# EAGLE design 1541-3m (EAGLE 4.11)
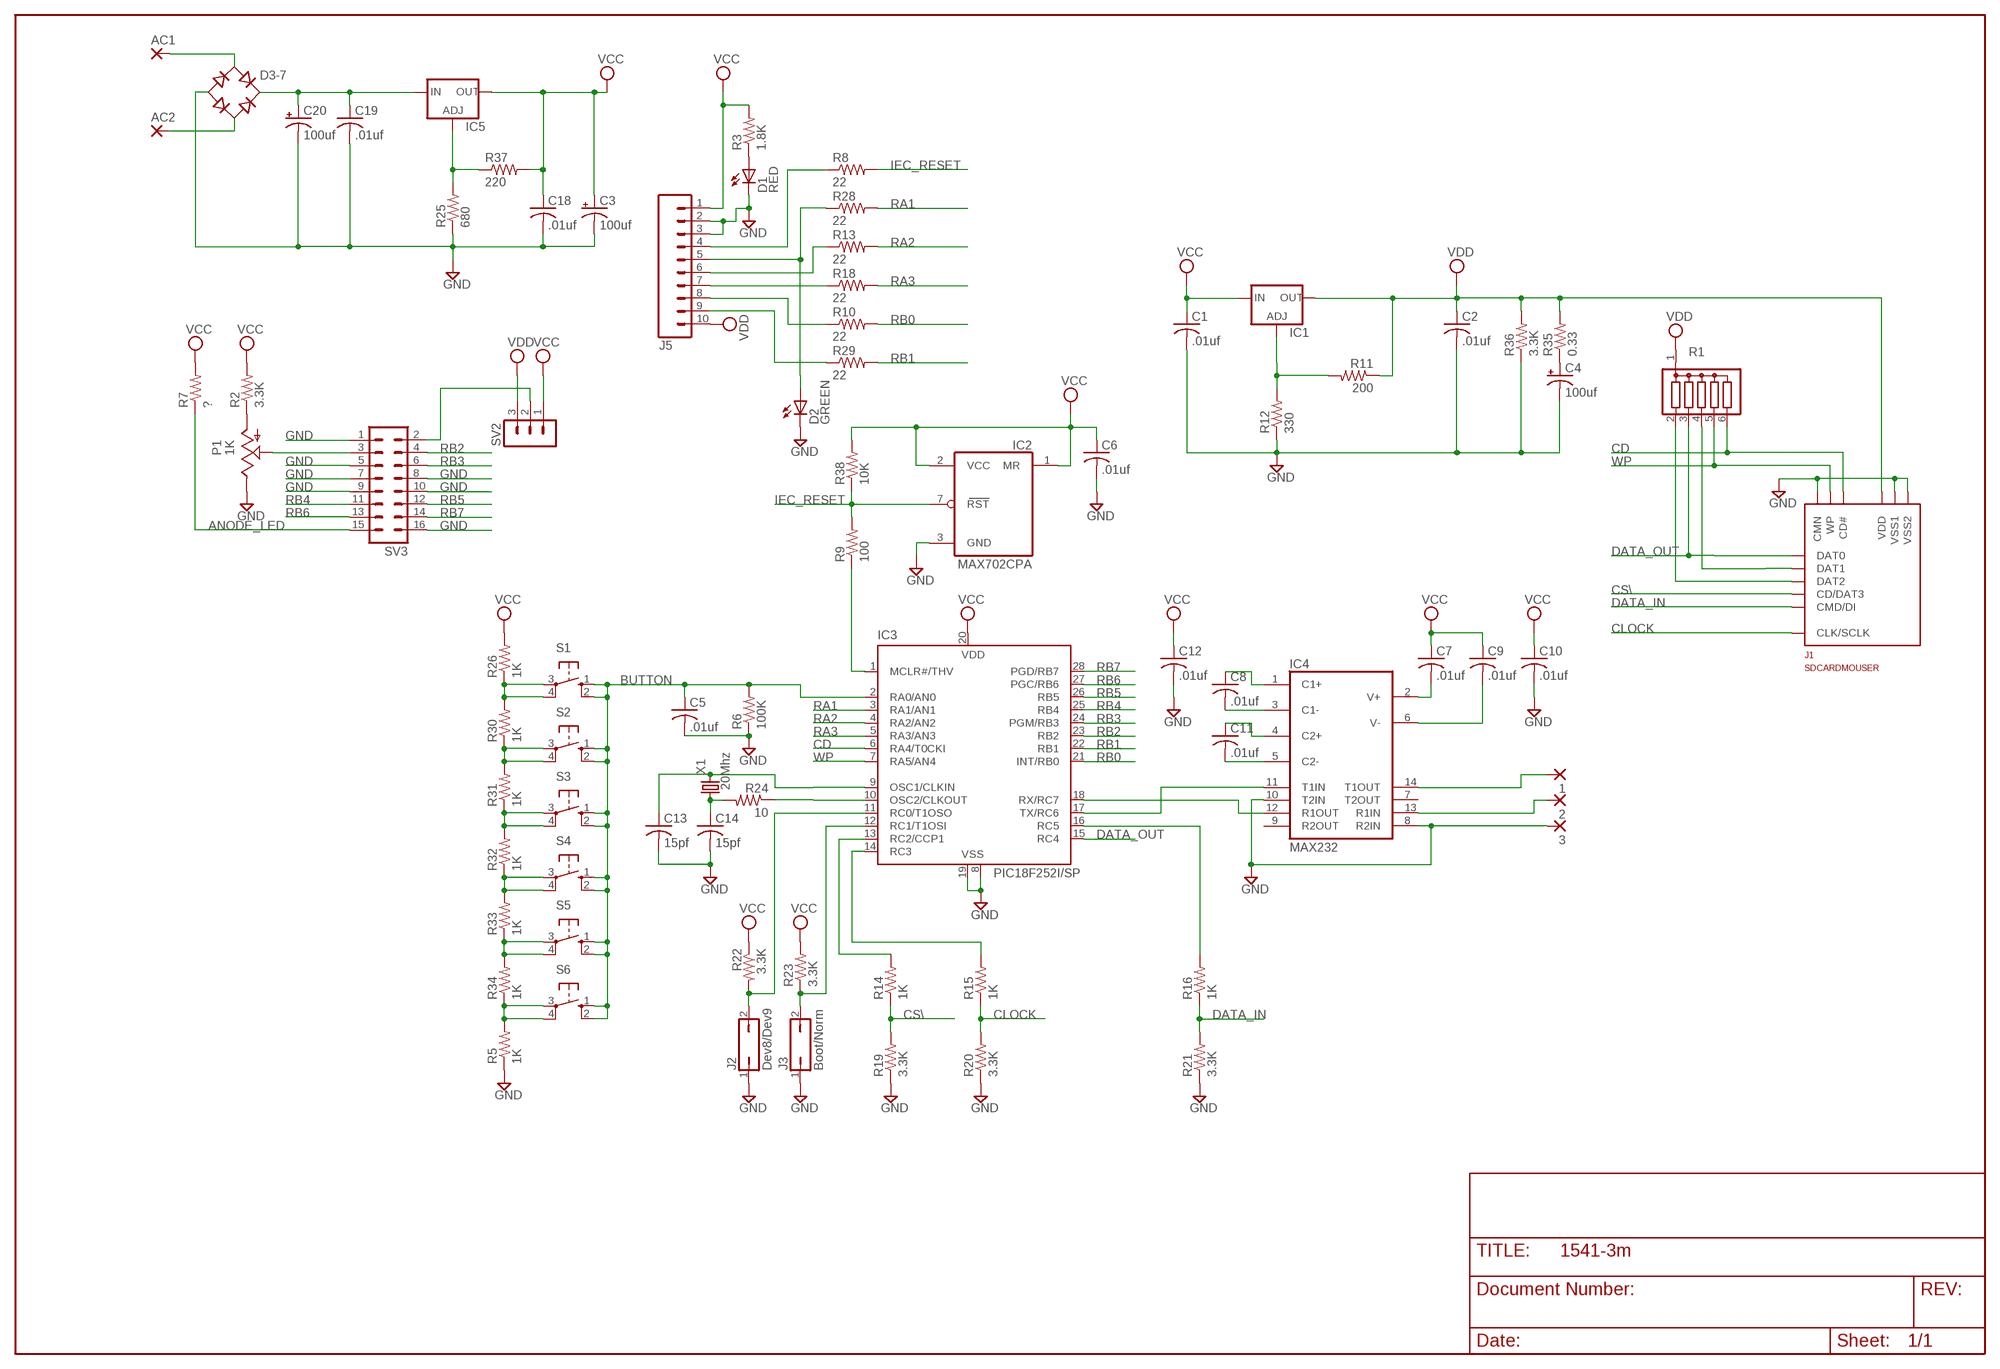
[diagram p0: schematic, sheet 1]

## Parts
1  2,15/1,0  [2,15/1,0]
2  2,15/1,0  [2,15/1,0]
3  2,15/1,0  [2,15/1,0]
AC1  2,15/1,0  [2,15/1,0]
AC2  2,15/1,0  [2,15/1,0]
C1  .01uf  C-US025-024X044  [C025-024X044]
C2  .01uf  C-US025-024X044  [C025-024X044]
C3  100uf  CPOL-USE2-5  [E2-5]
C4  100uf  CPOL-USE2-5  [E2-5]
C5  .01uf  C-US025-024X044  [C025-024X044]
C6  .01uf  C-US025-024X044  [C025-024X044]
C7  .01uf  C-US025-024X044  [C025-024X044]
C8  .01uf  C-US025-024X044  [C025-024X044]
C9  .01uf  C-US025-024X044  [C025-024X044]
C10  .01uf  C-US025-024X044  [C025-024X044]
C11  .01uf  C-US025-024X044  [C025-024X044]
C12  .01uf  C-US025-024X044  [C025-024X044]
C13  15pf  C-US025-024X044  [C025-024X044]
C14  15pf  C-US025-024X044  [C025-024X044]
C18  .01uf  C-US025-024X044  [C025-024X044]
C19  .01uf  C-US025-024X044  [C025-024X044]
C20  100uf  CPOL-USE2-5  [E2-5]
D1  RED  LED3MM  [LED3MM]
D2  GREEN  LED3MM  [LED3MM]
D3-7  RB1A  [RB1A]
IC1  LM317TS  [317TS]
IC2  MAX702CPA  [DIL08]
IC3  PIC18F252I/SP  PIC16F870P  [DIL28-3]
IC4  MAX232  [DIL16]
IC5  LM317TS  [317TS]
J1  SDCARDMOUSER  [SCDA1A]
J2  Dev8/Dev9  JP1Q  [JP1]
J3  Boot/Norm  JP1Q  [JP1]
J5  M10  [10P]
P1  1K  TRIM_US-LI10  [LI10]
R1  G05R  [SIL6]
R2  3.3K  R-US_0207/2V  [0207/2V]
R3  1.8K  R-US_0207/2V  [0207/2V]
R5  1K  R-US_0207/2V  [0207/2V]
R6  100K  R-US_0207/2V  [0207/2V]
R7  ?  R-US_0207/2V  [0207/2V]
R8  22  R-US_0207/2V  [0207/2V]
R9  100  R-US_0207/2V  [0207/2V]
R10  22  R-US_0207/2V  [0207/2V]
R11  200  R-US_0207/2V  [0207/2V]
R12  330  R-US_0207/2V  [0207/2V]
R13  22  R-US_0207/2V  [0207/2V]
R14  1K  R-US_0207/2V  [0207/2V]
R15  1K  R-US_0207/2V  [0207/2V]
R16  1K  R-US_0207/2V  [0207/2V]
R18  22  R-US_0207/2V  [0207/2V]
R19  3.3K  R-US_0207/2V  [0207/2V]
R20  3.3K  R-US_0207/2V  [0207/2V]
R21  3.3K  R-US_0207/2V  [0207/2V]
R22  3.3K  R-US_0207/2V  [0207/2V]
R23  3.3K  R-US_0207/2V  [0207/2V]
R24  10  R-US_0207/2V  [0207/2V]
R25  680  R-US_0207/2V  [0207/2V]
R26  1K  R-US_0207/2V  [0207/2V]
R28  22  R-US_0207/2V  [0207/2V]
R29  22  R-US_0207/2V  [0207/2V]
R30  1K  R-US_0207/2V  [0207/2V]
R31  1K  R-US_0207/2V  [0207/2V]
R32  1K  R-US_0207/2V  [0207/2V]
R33  1K  R-US_0207/2V  [0207/2V]
R34  1K  R-US_0207/2V  [0207/2V]
R35  0.33  R-US_0207/2V  [0207/2V]
R36  3.3K  R-US_0207/2V  [0207/2V]
R37  220  R-US_0207/2V  [0207/2V]
R38  10K  R-US_0207/2V  [0207/2V]
S1  10-XX  [B3F-10XX]
S2  10-XX  [B3F-10XX]
S3  10-XX  [B3F-10XX]
S4  10-XX  [B3F-10XX]
S5  10-XX  [B3F-10XX]
S6  10-XX  [B3F-10XX]
SV2  MA03-1  [MA03-1]
SV3  ML16  [ML16]
X1  20Mhz  CRYTALHC49U70  [HC49U70]

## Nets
ANODE_LED: R7.1 SV3.15
BUTTON: C5.1 IC3.2(RA0/AN0) R6.2 S1.1(S) S1.2(S1) S2.1(S) S2.2(S1) S3.1(S) S3.2(S1) S4.1(S) S4.2(S1) S5.1(S) S5.2(S1) S6.1(S) S6.2(S1)
CD: IC3.6(RA4/T0CKI) J1.10(CD#) R1.6
CLOCK: J1.5(CLK/SCLK) R15.1 R20.2
CS\: J1.1(CD/DAT3) R14.1 R19.2
DATA_IN: J1.2(CMD/DI) R16.1 R21.2
DATA_OUT: IC3.15(RC4) J1.7(DAT0) R1.3
GND: 3.1(P) C1.2 C2.2 C3.- C4.- C5.2 C6.2 C10.2 C12.2 C13.2 C14.2 C18.2 C19.2 C20.- D1.K(C) D2.K(C) D3-7.- IC2.3(GND) IC3.8(VSS) IC3.19(VSS) IC4.8(R2IN) IC4.10(T2IN) J1.3(VSS1) J1.6(VSS2) J1.11(CMN) J2.1 J3.1 J5.2 J5.3 P1.E R5.1 R6.1 R12.1 R19.1 R20.1 R21.1 R25.1 R36.1 SV3.1 SV3.5 SV3.7 SV3.8 SV3.9 SV3.10 SV3.16
IEC_RESET: IC2.7(RST) R8.2 R9.2 R38.1
N$1: C4.+ R35.1
N$2: J1.9(DAT2) R1.2
N$3: J1.8(DAT1) R1.4
N$4: J5.9 R29.1
N$5: J5.8 R10.1
N$6: J5.7 R18.1
N$7: J5.4 R8.1
N$8: D2.A J5.5 R28.1
N$9: J5.6 R13.1
N$10: D1.A R3.1
N$11: IC3.18(RX/RC7) IC4.12(R1OUT)
N$12: IC3.14(RC3) R15.2
N$13: C14.1 R24.2 X1.1
N$14: IC3.1(MCLR#/THV) R9.1
N$15: C11.1 IC4.4(C2+)
N$16: C11.2 IC4.5(C2-)
N$17: C8.2 IC4.3(C1-)
N$18: C8.1 IC4.1(C1+)
N$19: C7.2 IC4.2(V+)
N$20: C13.1 IC3.9(OSC1/CLKIN) X1.2
N$21: IC3.10(OSC2/CLKOUT) R24.1
N$22: IC3.12(RC1/T1OSI) J3.2 R23.1
N$23: IC3.11(RC0/T1OSO) J2.2 R22.2
N$24: IC3.13(RC2/CCP1) R14.2
N$25: IC3.16(RC5) R16.2
N$26: IC1.1(ADJ) R11.2 R12.2
N$27: IC3.17(TX/RC6) IC4.11(T1IN)
N$28: R26.1 R30.2 S1.3(P) S1.4(P1)
N$29: R30.1 R31.2 S2.3(P) S2.4(P1)
N$30: R31.1 R32.2 S3.3(P) S3.4(P1)
N$31: R5.2 R34.1 S6.3(P) S6.4(P1)
N$32: R33.1 R34.2 S5.3(P) S5.4(P1)
N$33: R32.1 R33.2 S4.3(P) S4.4(P1)
N$34: P1.A R2.1
N$35: SV2.2 SV3.2
N$36: P1.S SV3.3
N$37: C9.2 IC4.6(V-)
N$38: IC5.1(ADJ) R25.2 R37.1
N$39: AC1.1(P) D3-7.AC1
N$40: C19.1 C20.+ D3-7.+ IC5.3(IN)
N$41: AC2.1(P) D3-7.AC2
N$42: 2.1(P) IC4.13(R1IN)
N$43: 1.1(P) IC4.14(T1OUT)
RA1: IC3.3(RA1/AN1) R28.2
RA2: IC3.4(RA2/AN2) R13.2
RA3: IC3.5(RA3/AN3) R18.2
RB0: IC3.21(INT/RB0) R10.2
RB1: IC3.22(RB1) R29.2
RB2: IC3.23(RB2) SV3.4
RB3: IC3.24(PGM/RB3) SV3.6
RB4: IC3.25(RB4) SV3.11
RB5: IC3.26(RB5) SV3.12
RB6: IC3.27(PGC/RB6) SV3.13
RB7: IC3.28(PGD/RB7) SV3.14
VCC: C1.1 C3.+ C6.1 C7.1 C9.1 C10.1 C12.1 C18.1 IC1.3(IN) IC2.1(MR) IC2.2(VCC) IC3.20(VDD) IC5.2(OUT) J5.1 R2.2 R3.2 R7.2 R22.1 R23.2 R26.2 R37.2 R38.2 SV2.1
VDD: C2.1 IC1.2(OUT) J1.4(VDD) J5.10 R1.1 R11.1 R35.2 R36.2 SV2.3
WP: IC3.7(RA5/AN4) J1.12(WP) R1.5
Unconnected: IC4.7(T2OUT) IC4.9(R2OUT)

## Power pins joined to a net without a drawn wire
GND: IC4.15(GND) J1.13(GND) J1.14(GND)
VCC: IC4.16(VCC)

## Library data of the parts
1-3 AC1 AC2 = wirepad:2,15/1,0: THROUGH-HOLE PAD
C1 C2 C5-C14 C18 C19 = rcl:C-US: CAPACITOR, American symbol
C3 C4 C20 = rcl:CPOL-US: POLARIZED CAPACITOR, American symbol
D1 D2 = led:LED: LED
D3-7 = rectifier:RB1A: RECTIFIER 1 A
IC1 IC5 = v-reg:LM317TS: VOLTAGE REGULATOR
IC2 = maxim:MAX702CPA: POWER SUPPLY MONITOR
IC3 = microchip:PIC16*870: MICROCONTROLLER flash type
IC4 = maxim:MAX232: RS232 TRANSEIVER
J1 = sdcards:SDCARD: SD Card Holder
J2 J3 = jumper:JP1Q: JUMPER
J5 = con-amp-quick:M10: AMP QUICK CONNECTOR
P1 = pot:TRIM_US-: POTENTIOMETER
R1 = resistor-sil:G05R: SIL RESISTOR
R2 R3 R5-R16 R18-R26 R28-R38 = rcl:R-US_: RESISTOR, American symbol
S1-S6 = switch-omron:10-XX: OMRON SWITCH
SV2 = con-lstb:MA03-1: PIN HEADER
SV3 = con-harting-ml:ML16: HARTING
X1 = crystal:CRYTAL: CRYSTAL

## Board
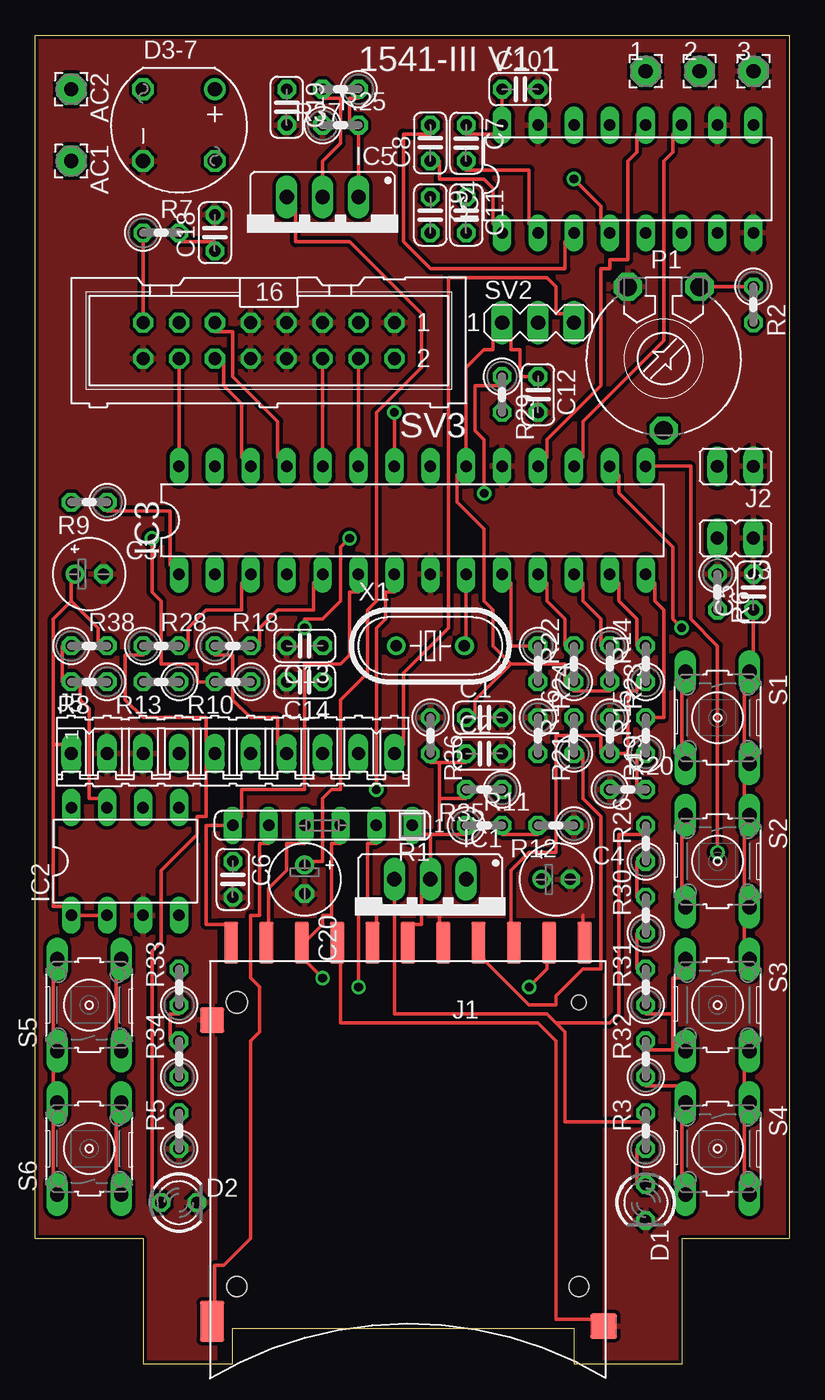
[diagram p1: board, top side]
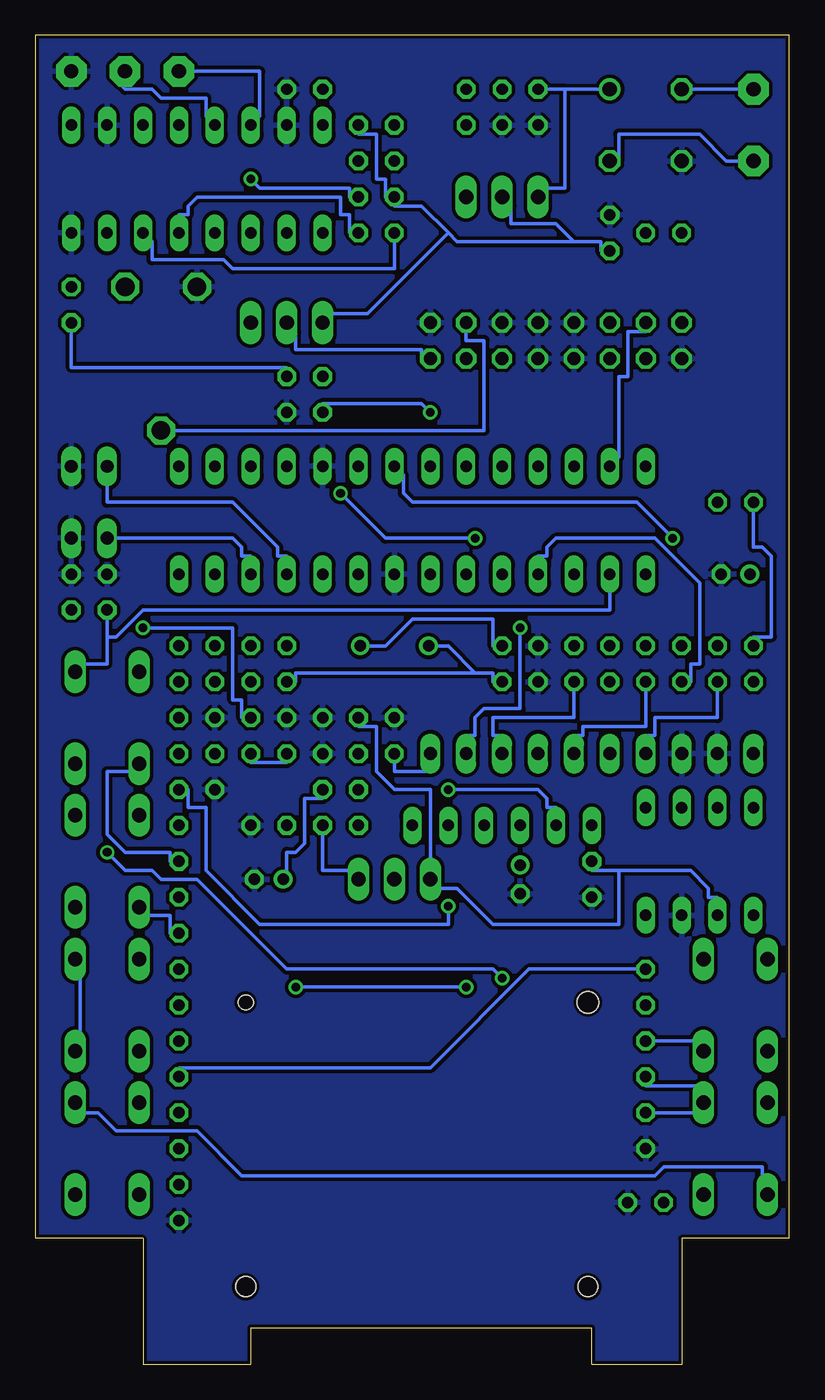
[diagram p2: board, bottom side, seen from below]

Size 53.34 x 93.98 mm. Coordinates in mm from the lower left corner, seen from the top.
Outline: 0,93.98 53.34,93.98 53.34,8.89 45.72,8.89 45.72,0 38.1,0 38.1,2.54 13.97,2.54 13.97,0 7.62,0 7.62,8.89 0,8.89 0,93.98
Copper layers (1*16): Top 0.035mm / dielectric 1.5mm / Bottom 0.035mm
Design rules "olimex10mil": minimum track width 10mil, minimum drill 24mil, track to track 10mil, track to pad 10mil, pad to pad 10mil, via to via 10mil, smd to smd 10mil, copper to edge 10mil, drill to drill 10mil, minimum pad ring 10mil, minimum via ring 8mil, stop-mask expansion 0mil, vias tented up to drill 0mil, thermal gap 10mil

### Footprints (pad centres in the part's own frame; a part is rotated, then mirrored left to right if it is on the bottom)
2,15/1,0 = drill 1.016 pad 2.159 octagon: 1 0,0
C025-024X044 = drill 0.813 octagon: 1 -1.27,0; 2 1.27,0
E2-5 = drill 0.813 pad 1.27 round: + -1.016,0 | drill 0.813 pad 1.27 octagon: - 1.016,0
LED3MM = drill 0.813 octagon: A -1.27,0; K 1.27,0
RB1A = drill 1.016 round: + -2.54,2.54 | drill 1.016 octagon: - 2.54,-2.54; AC1 2.54,2.54; AC2 -2.54,-2.54
317TS = drill 1.016 long: 1 -2.54,-2.54; 2 0,-2.54; 3 2.54,-2.54
DIL08 = drill 0.813 long: 1 -3.81,-3.81; 2 -1.27,-3.81; 3 1.27,-3.81; 4 3.81,-3.81; 5 3.81,3.81; 6 1.27,3.81; 7 -1.27,3.81; 8 -3.81,3.81
DIL28-3 = drill 0.813 long: 1 -16.51,-3.81; 2 -13.97,-3.81; 3 -11.43,-3.81; 4 -8.89,-3.81; 5 -6.35,-3.81; 6 -3.81,-3.81; 7 -1.27,-3.81; 8 1.27,-3.81; 9 3.81,-3.81; 10 6.35,-3.81; 11 8.89,-3.81; 12 11.43,-3.81; 13 13.97,-3.81; 14 16.51,-3.81; 15 16.51,3.81; 16 13.97,3.81; 17 11.43,3.81; 18 8.89,3.81; 19 6.35,3.81; 20 3.81,3.81; 21 1.27,3.81; 22 -1.27,3.81; 23 -3.81,3.81; 24 -6.35,3.81; 25 -8.89,3.81; 26 -11.43,3.81; 27 -13.97,3.81; 28 -16.51,3.81
DIL16 = drill 0.813 long: 1 -8.89,-3.81; 2 -6.35,-3.81; 3 -3.81,-3.81; 4 -1.27,-3.81; 5 1.27,-3.81; 6 3.81,-3.81; 7 6.35,-3.81; 8 8.89,-3.81; 9 8.89,3.81; 10 6.35,3.81; 11 3.81,3.81; 12 1.27,3.81; 13 -1.27,3.81; 14 -3.81,3.81; 15 -6.35,3.81; 16 -8.89,3.81
SCDA1A = smd 1 x 2.95: 1 -7.5,-10.125; 2 -5,-10.125; 3 -2.5,-10.125; 4 0,-10.125; 5 2.5,-10.125; 6 5,-10.125; 7 7.5,-10.125; 8 10,-10.125; 9 -10,-10.125; 10 12.5,-10.125; 13 -12.5,-10.125 | smd 1.7 x 1.8: 11 13.85,-4.65 | smd 1.7 x 2.9: 12 13.85,16.65 | smd 1.9 x 1.8: 14 -13.85,17 | hole 1.05: -12.1,-5.9 | hole 1.5: 12.1,-5.9 | hole 1.4: 12.1,14.2; -12.1,14.2
JP1 = drill 0.914 long: 1 0,-1.27; 2 0,1.27
10P = drill 0.914 long: 1 -11.43,0; 2 -8.89,0; 3 -6.35,0; 4 -3.81,0; 5 -1.27,0; 6 1.27,0; 7 3.81,0; 8 6.35,0; 9 8.89,0; 10 11.43,0
LI10 = drill 1.321 octagon: A -2.54,-5.08; E 2.54,-5.08; S 0,5.08
SIL6 = drill 0.813 long: 1 -6.35,0; 2 -3.81,0; 3 -1.27,0; 4 1.27,0; 5 3.81,0; 6 6.35,0
0207/2V = drill 0.813 octagon: 1 -1.27,0; 2 1.27,0
B3F-10XX = drill 1.016 long: 1 -3.251,2.261; 2 3.251,2.261; 3 -3.251,-2.261; 4 3.251,-2.261
MA03-1 = drill 1.016 long: 1 -2.54,0; 2 0,0; 3 2.54,0
ML16 = drill 0.914 octagon: 1 -8.89,-1.27; 2 -8.89,1.27; 3 -6.35,-1.27; 4 -6.35,1.27; 5 -3.81,-1.27; 6 -3.81,1.27; 7 -1.27,-1.27; 8 -1.27,1.27; 9 1.27,-1.27; 10 1.27,1.27; 11 3.81,-1.27; 12 3.81,1.27; 13 6.35,-1.27; 14 6.35,1.27; 15 8.89,-1.27; 16 8.89,1.27
HC49U70 = drill 0.813 round: 1 -2.413,0; 2 2.413,0

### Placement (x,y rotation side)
1  43.18,91.44 0 top
2  46.99,91.44 0 top
3  50.8,91.44 0 top
AC1  2.54,85.09 270 top
AC2  2.54,90.17 270 top
C1  31.75,45.72 0 top
C2  31.75,43.18 0 top
C3  3.81,55.88 0 top
C4  36.83,34.29 0 top
C5  50.8,54.61 90 top
C6  13.97,34.29 270 top
C7  30.48,86.36 270 top
C8  27.94,86.36 90 top
C9  27.94,81.28 270 top
C10  34.29,90.17 0 top
C11  30.48,81.28 270 top
C12  35.56,68.58 270 top
C13  19.05,50.8 180 top
C14  19.05,48.26 180 top
C18  12.7,80.01 90 top
C19  17.78,88.9 270 top
C20  19.05,34.29 270 top
D1  43.18,11.43 270 top
D2  10.16,11.43 0 top
D3-7  10.16,87.63 270 top
IC1  27.94,31.75 180 top
IC2  6.35,35.56 0 top
IC3  26.67,59.69 0 top
IC4  41.91,83.82 0 top
IC5  20.32,80.01 180 top
J1  26.35,19.68 180 top
J2  49.53,63.5 90 top
J3  49.53,58.42 90 top
J5  13.97,43.18 0 top
P1  44.45,71.12 180 top
R1  20.32,38.1 180 top
R2  50.8,74.93 270 top
R3  43.18,16.51 90 top
R5  10.16,16.51 90 top
R6  48.26,54.61 270 top
R7  8.89,80.01 0 top
R8  3.81,48.26 180 top
R9  3.81,60.96 180 top
R10  13.97,48.26 180 top
R11  31.75,38.1 0 top
R12  36.83,38.1 180 top
R13  8.89,48.26 180 top
R14  43.18,49.53 90 top
R15  43.18,44.45 90 top
R16  38.1,44.45 90 top
R18  13.97,50.8 0 top
R19  40.64,44.45 270 top
R20  41.91,40.64 0 top
R21  35.56,44.45 270 top
R22  38.1,49.53 90 top
R23  40.64,49.53 270 top
R24  35.56,49.53 270 top
R25  21.59,87.63 0 top
R26  43.18,36.83 90 top
R28  8.89,50.8 0 top
R29  33.02,68.58 270 top
R30  43.18,31.75 90 top
R31  43.18,26.67 90 top
R32  43.18,21.59 90 top
R33  10.16,26.67 90 top
R34  10.16,21.59 90 top
R35  31.75,40.64 180 top
R36  27.94,44.45 270 top
R37  21.59,90.17 180 top
R38  3.81,50.8 0 top
S1  48.26,45.72 270 top
S2  48.26,35.56 270 top
S3  48.26,25.4 270 top
S4  48.26,15.24 270 top
S5  3.81,25.4 90 top
S6  3.81,15.24 90 top
SV2  35.56,73.66 0 top
SV3  16.51,72.39 180 top
X1  27.94,50.8 0 top

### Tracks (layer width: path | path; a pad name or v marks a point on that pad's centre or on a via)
ANODE_LED
  Top 0.254: R7.1 7.62,79.38 7.62,74.3 SV3.15
BUTTON
  Top 0.254: C5.1 50.8,52.7 50.8,50.16 S1.1 50.16,47.62 50.16,43.81 S1.2 50.16,41.27 50.16,40.01 S2.1 50.16,37.47 50.16,33.66 S2.2 50.16,31.11 50.16,29.84 S3.1 | S6.1 1.27,13.34 1.27,17.14 S6.2 1.27,19.68 1.27,20.95 S5.1 1.27,23.5 1.27,27.3 S5.2 | S4.2 50.16,13.34 50.16,17.14 S4.1 50.16,19.68 50.16,20.95 S3.2
  Bottom 0.254: 48.26,51.44 48.26,49.53 50.16,49.53 S1.1 | 48.26,51.44 48.26,52.7 R6.2 | 48.26,51.44 47.62,51.44 45.72,53.34 12.7,53.34 12.7,54.61 IC3.2 | S3.2 50.16,23.5 50.16,27.3 S3.1 | S6.1 1.91,13.34 1.91,13.97 8.89,13.97 9.53,13.34 38.73,13.34 41.91,16.51 47.62,16.51 48.9,17.78 50.16,17.78 S4.1
CD
  Top 0.254: J1.10 13.97,31.11 12.06,31.11 12.06,38.1 13.34,38.1 R1.6 14.61,38.73 14.61,40.64 19.05,40.64 19.05,49.53 21.59,49.53 22.23,50.16 22.23,54.61 22.86,54.61 IC3.6
CLOCK  (via drill 0.61)
  Top 0.254: R20.2 42.55,40.64 42.55,43.18 R15.1 | v24.13,32.38 24.13,31.11 J1.5
  Bottom 0.254: v24.13,32.38 24.13,31.11 37.47,31.11 41.27,34.92 41.27,39.37 42.55,39.37 42.55,40.64 R20.2
CS\
  Top 0.254: R14.1 42.55,48.26 42.55,47.62 41.91,47.62 41.91,43.18 41.27,43.18 R19.2 40.01,43.18 40.01,44.45 36.83,44.45 36.83,36.2 34.92,36.2 33.66,34.92 33.66,31.11 J1.1
DATA_IN
  Top 0.254: J1.2 31.75,28.57 34.92,25.4 36.83,25.4 36.83,26.04 38.73,27.94 40.01,27.94 40.01,38.73 38.73,40.01 38.73,43.18 R16.1
  Bottom 0.254: R21.2 35.56,42.55 38.1,42.55 R16.1
DATA_OUT  (via drill 0.61)
  Top 0.254: R1.3 21.59,36.83 20.95,36.83 20.95,31.75 20.32,31.75 20.32,31.11 19.05,29.84 J1.7 19.05,28.57 v20.32,27.3 | v48.26,36.2 48.26,50.8 46.35,52.7 46.35,63.5 43.81,63.5 IC3.15
  Bottom 0.254: v48.26,36.2 46.99,34.92 45.09,34.92 44.45,34.29 41.91,34.29 35.56,27.94 20.95,27.94 v20.32,27.3
GND
  Top 0.254: 40.41,1.91 40.64,1.91 J1.14 39.37,3.17 36.83,3.17 36.83,22.86 35.56,24.13 21.59,24.13 21.59,28.57 J1.6 | 28.57,31.75 28.57,31.11 J1.3 | 38.73,31.75 38.73,31.11 J1.13
  pour Bottom: 0,0 53.34,0 53.34,93.98 0,93.98
  pour Top: 0,0 12.7,0 12.7,31.75 40.32,31.75 40.32,0 53.34,0 53.34,93.98 0,93.98
IEC_RESET
  Top 0.254: R38.1 1.91,50.8 1.91,48.26 R8.2 3.17,48.26 3.17,46.99 3.81,46.35 3.81,40.01 4.45,40.01 IC2.7
  Bottom 0.254: R9.2 2.54,60.33 2.54,57.78 1.91,57.78 1.27,57.15 1.27,51.44 2.54,51.44 R38.1
N$1
  Bottom 0.254: C4.+ 35.56,34.92 35.56,36.2 34.92,36.2 34.29,36.83 34.29,40.01 33.02,40.01 R35.1
N$2  (via drill 0.61)
  Top 0.254: v22.86,26.67 22.86,32.38 23.5,33.02 23.5,36.83 24.13,36.83 R1.2 | v34.92,26.67 36.2,27.94 36.2,28.57 J1.9
  Bottom 0.254: v22.86,26.67 v34.92,26.67
N$3
  Top 0.254: R1.4 19.05,36.83 17.78,36.83 17.78,34.92 16.51,33.66 16.51,31.11 J1.8
N$4  (via drill 0.61)
  Top 0.254: v31.75,61.59 31.75,65.41 31.11,66.04 31.11,69.22 33.02,69.22 R29.1 | v22.23,58.42 21.59,57.78 21.59,53.98 20.32,52.7 19.05,52.7 v19.05,52.07
  Bottom 0.254: v31.75,61.59 28.57,58.42 v22.23,58.42 | v19.05,52.07 19.05,46.35 21.59,46.35 22.23,45.72 22.23,44.45 22.86,44.45 J5.9
N$5
  Bottom 0.254: R10.1 15.24,47.62 15.24,45.72 20.95,45.72 20.95,44.45 20.32,44.45 J5.8
N$6
  Top 0.254: R18.1 12.7,50.16 13.97,50.16 13.97,46.99 15.24,45.72 17.14,45.72 17.14,43.81 J5.7
N$7
  Bottom 0.254: R8.1 5.08,47.62 5.08,45.72 9.53,45.72 9.53,44.45 10.16,44.45 J5.4
N$8
  Top 0.254: D2.A 8.26,11.43 8.26,29.21 8.89,29.84 8.89,34.92 11.43,37.47 11.43,38.73 12.06,38.73 12.06,42.55 J5.5 12.06,43.81 12.06,45.72 7.62,45.72 6.35,46.99 6.35,50.16 7.62,50.16 R28.1
N$9
  Bottom 0.254: R13.1 10.16,47.62 10.16,45.09 14.61,45.09 14.61,44.45 15.24,44.45 J5.6
N$10
  Top 0.254: D1.A 42.55,12.7 42.55,15.24 R3.1
N$11
  Top 0.254: IC3.18 36.2,64.14 36.2,65.41 40.01,69.22 40.01,77.47 40.64,77.47 40.64,78.11 41.91,78.11 41.91,85.09 42.55,85.72 42.55,87 IC4.12
N$12
  Top 0.254: R15.2 43.81,45.72 44.45,45.72 44.45,53.34 43.81,53.98 43.81,55.24 IC3.14
N$13
  Bottom 0.254: 22.23,48.9 20.95,48.9 20.95,48.26 C14.1 | 22.23,48.9 24.13,50.8 25.4,50.8 X1.1 | 22.23,48.9 34.92,48.9 34.92,48.26 R24.2
N$14
  Top 0.254: R9.1 5.08,60.33 9.53,60.33 9.53,56.52 IC3.1
N$15  (via drill 0.61)
  Top 0.254: v38.1,83.82 40.01,81.92 40.01,80.64 IC4.4
  Bottom 0.254: v38.1,83.82 37.47,83.19 31.11,83.19 31.11,82.55 C11.1
N$16
  Bottom 0.254: C11.2 31.11,80.01 31.11,81.28 31.75,81.28 31.75,82.55 41.91,82.55 42.55,81.92 42.55,81.28 43.18,81.28 IC4.5
N$17
  Top 0.254: C8.2 27.94,87 26.04,87 26.04,79.38 27.94,77.47 37.47,77.47 37.47,79.38 IC4.3
N$18
  Top 0.254: IC4.1 32.38,80.64 32.38,83.19 31.75,83.82 28.57,83.82 28.57,85.09 C8.1
N$19
  Top 0.254: C7.2 30.48,84.45 34.92,84.45 34.92,80.64 IC4.2
N$20
  Top 0.254: IC3.9 30.48,54.61 30.48,51.44 X1.2
  Bottom 0.254: C13.1 20.95,50.8 20.95,52.7 26.67,52.7 28.57,50.8 29.84,50.8 X1.2
N$21
  Top 0.254: R24.1 34.92,50.8 33.66,50.8 33.66,55.24 IC3.10
N$22
  Top 0.254: R23.1 40.01,50.8 40.01,52.7 38.73,53.98 38.73,55.24 IC3.12
  Bottom 0.254: J3.2 47.62,58.42 39.37,58.42 38.73,57.78 38.73,57.15 38.1,57.15 IC3.12
N$23
  Top 0.254: R22.2 37.47,50.8 37.47,52.7 36.2,53.98 36.2,55.24 IC3.11
  Bottom 0.254: J2.2 48.26,62.23 48.26,60.96 39.37,60.96 36.2,57.78 36.2,57.15 35.56,57.15 IC3.11
N$24
  Top 0.254: R14.2 42.55,50.8 42.55,52.7 41.27,53.98 41.27,55.24 IC3.13
N$25  (via drill 0.61)
  Top 0.254: v45.72,52.07 45.09,52.7 45.09,57.78 41.27,61.59 41.27,62.87 IC3.16
  Bottom 0.254: v45.72,52.07 39.37,52.07 39.37,46.99 38.73,46.99 38.73,45.72 R16.2
N$26
  Top 0.254: R12.2 35.56,37.47 33.02,37.47 R11.2
  Bottom 0.254: R11.2 33.02,37.47 33.02,34.92 31.11,34.92 IC1.1
N$27
  Top 0.254: IC3.17 38.73,64.14 38.73,66.67 44.45,72.39 44.45,85.09 45.09,85.72 45.09,87 IC4.11
N$28
  Top 0.254: R30.2 42.55,33.02 42.55,35.56 R26.1 | S1.4 45.72,43.81 45.72,47.62 S1.3
  Bottom 0.254: R26.1 43.81,35.56 43.81,36.2 46.99,36.2 48.26,37.47 48.26,41.91 46.35,41.91 S1.4
N$29
  Top 0.254: R31.2 42.55,27.94 42.55,30.48 R30.1 | S2.4 45.72,33.66 45.72,37.47 S2.3
  Bottom 0.254: R30.1 43.81,30.48 43.81,31.75 45.72,31.75 S2.4
N$30
  Top 0.254: 45.09,22.23 45.72,22.23 S3.4 | 45.09,22.23 43.18,22.23 R32.2 | 45.09,24.77 43.18,24.77 R31.1 | 45.09,22.23 45.09,24.77 | 45.09,24.77 45.09,27.3 45.72,27.3 S3.3
N$31
  Top 0.254: S6.3 5.71,13.34 5.71,17.14 S6.4
  Bottom 0.254: R5.2 9.53,17.78 6.35,17.78 S6.4 6.35,19.68 10.16,19.68 R34.1
N$32
  Top 0.254: R33.1 10.16,24.77 9.53,24.77 9.53,22.86 R34.2 | S5.4 5.71,27.3 5.71,23.5 S5.3
  Bottom 0.254: R34.2 9.53,22.86 6.35,22.86 S5.3
N$33
  Top 0.254: S4.4 45.72,13.34 45.72,17.14 S4.3 45.72,19.68 43.18,19.68 R32.1
  Bottom 0.254: R33.2 10.79,27.94 18.41,27.94 25.4,20.95 43.18,20.95 R32.1
N$34
  Top 0.254: R2.1 50.16,76.2 47.62,76.2 P1.A
N$35
  Bottom 0.254: SV3.2 26.04,71.12 26.04,71.75 34.92,71.75 34.92,73.03 SV2.2
N$36
  Bottom 0.254: SV3.3 22.86,73.03 22.86,72.39 21.59,72.39 21.59,66.04 43.81,66.04 P1.S
N$37
  Bottom 0.254: C9.2 27.94,79.38 27.94,77.47 39.37,77.47 40.01,78.11 45.09,78.11 45.09,79.38 IC4.6
N$38
  Top 0.254: IC5.1 22.86,83.82 22.86,87 R25.2 22.23,87.63 22.23,89.53 22.86,89.53 R37.1
N$39
  Bottom 0.254: D3-7.AC1 12.06,85.09 12.06,87 6.35,87 4.45,85.09 3.17,85.09 AC1.1
N$40
  Top 0.254: C20.+ 19.68,35.56 20.32,35.56 20.32,40.01 20.95,40.64 21.59,40.64 21.59,46.99 23.5,48.9 23.5,53.34 24.13,53.98 24.13,67.31 27.3,70.48 27.3,74.3 22.23,79.38 18.41,79.38 18.41,81.92 IC5.3
  Bottom 0.254: 15.88,90.17 13.34,90.17 D3-7.+ | 15.88,90.17 17.14,90.17 C19.1 | 15.88,90.17 15.88,83.19 17.14,83.19 IC5.3
N$41
  Bottom 0.254: D3-7.AC2 6.99,90.17 3.17,90.17 AC2.1
N$42
  Bottom 0.254: IC4.13 41.27,88.27 41.27,89.53 44.45,89.53 45.09,90.17 46.99,90.17 47.62,90.81 2.1
N$43
  Bottom 0.254: IC4.14 37.47,88.27 37.47,91.44 42.55,91.44 1.1
RA1
  Top 0.254: R28.2 10.79,50.8 10.79,52.07 12.06,53.34 14.61,53.34 14.61,55.24 IC3.3
RA2
  Bottom 0.254: R13.2 6.99,48.26 6.99,49.53 6.35,49.53 6.35,55.24 9.53,58.42 16.51,58.42 17.14,57.78 17.14,57.15 17.78,57.15 IC3.4
RA3
  Top 0.254: R18.2 15.88,50.8 15.88,52.07 17.14,53.34 19.68,53.34 19.68,55.24 IC3.5
RB0  (via drill 0.61)
  Top 0.254: v8.26,58.42 8.26,54.61 8.89,53.98 8.89,49.53 11.43,49.53 11.43,48.26 12.06,48.26 R10.2
  Bottom 0.254: v8.26,58.42 10.79,60.96 26.67,60.96 27.3,61.59 27.3,62.87 IC3.21
RB1  (via drill 0.61)
  Top 0.254: v25.4,67.31 25.4,64.77 IC3.22
  Bottom 0.254: v25.4,67.31 26.04,67.94 33.02,67.94 R29.2
RB2
  Top 0.254: IC3.23 22.86,64.77 22.86,70.48 SV3.4
RB3
  Top 0.254: IC3.24 20.32,64.77 20.32,70.48 SV3.6
RB4
  Top 0.254: IC3.25 17.14,64.14 17.14,66.67 13.97,69.85 13.97,73.03 12.7,73.03 SV3.11
RB5
  Top 0.254: IC3.26 14.61,64.14 14.61,67.94 13.34,69.22 13.34,71.12 SV3.12
RB6
  Bottom 0.254: IC3.27 12.06,64.14 12.06,69.85 11.43,69.85 11.43,73.03 10.16,73.03 SV3.13
RB7
  Top 0.254: IC3.28 10.16,64.77 10.16,70.48 SV3.14
VCC
  Top 0.254: IC2.2 4.45,31.75 3.17,31.75 IC2.1 1.91,32.38 1.27,32.38 1.27,43.81 | 2.54,53.98 4.45,52.07 4.45,50.8 R38.2 | 2.54,53.98 2.54,55.24 C3.+ | 1.27,43.81 1.91,43.81 J5.1 | 1.27,43.81 1.27,52.7 2.54,53.98 | 36.83,24.13 36.2,24.77 25.4,24.77 25.4,33.02 IC1.3 | 36.83,24.13 37.47,23.5 37.47,17.14 43.18,17.14 R3.2 | 36.83,24.13 40.64,24.13 41.27,24.77 41.27,37.47 43.18,37.47 R26.2 | C10.1 33.02,89.53 33.02,88.9 IC4.16 32.38,87 30.48,87 C7.1 | R7.2 10.16,79.38 12.7,79.38 C18.1 | R37.2 20.32,89.53 21.59,89.53 21.59,86.36 20.32,85.09 20.32,83.82 IC5.2 | 33.66,49.53 31.11,46.99 31.11,45.72 C1.1 | 33.66,49.53 37.47,49.53 37.47,48.26 R22.1 38.1,47.62 40.64,47.62 R23.2 | C12.1 34.92,69.85 34.29,69.85 34.29,71.75 33.66,71.75 33.66,73.03 SV2.1 32.38,73.03 32.38,71.75 31.75,71.75 30.48,70.48 30.48,64.77 IC3.20 29.84,62.87 29.84,60.96 31.75,59.05 31.75,53.98 32.38,53.34 32.38,50.8 33.66,49.53
  Bottom 0.254: 12.06,34.92 6.99,34.92 5.71,33.66 5.71,33.02 5.08,33.02 IC2.2 | 12.06,34.92 13.97,34.92 C6.1 | 12.06,34.92 12.06,31.11 20.95,31.11 23.5,33.66 24.77,33.66 IC1.3 25.4,35.56 25.4,40.64 27.94,40.64 29.21,41.91 29.21,45.09 30.48,45.09 C1.1 | C7.1 30.48,87 29.21,87 29.21,83.82 28.57,83.82 28.57,82.55 C9.1 27.94,81.92 26.04,81.92 24.13,80.01 | 15.24,79.38 13.34,79.38 13.34,78.74 C18.1 | 15.24,79.38 16.51,80.64 19.68,80.64 19.68,81.92 IC5.2 | 24.13,80.01 23.5,79.38 15.24,79.38 | R2.2 50.8,73.03 50.8,70.48 35.56,70.48 C12.1 | 24.13,80.01 29.84,74.3 32.38,74.3 SV2.1
VDD
  Top 0.254: 27.94,37.47 27.3,37.47 R1.1 | 27.94,37.47 27.94,35.56 IC1.2 27.3,33.66 27.3,31.11 26.67,31.11 J1.4 | 27.94,37.47 28.57,37.47 | 28.57,37.47 30.48,37.47 R11.1 | 28.57,40.01 30.48,40.01 R35.2 | 28.57,37.47 28.57,40.01 | 28.57,42.55 27.94,42.55 R36.2 | 28.57,42.55 30.48,42.55 C2.1 | SV2.3 37.47,74.3 36.83,74.3 36.83,76.2 36.2,76.83 29.21,76.83 29.21,52.07 26.04,48.9 26.04,43.81 J5.10 | 28.57,40.01 28.57,42.55
  Bottom 0.254: R36.2 27.94,42.55 27.94,41.91 25.4,41.91 J5.10
WP  (via drill 0.61)
  Top 0.254: R1.5 16.51,36.83 15.88,36.83 15.88,31.75 15.24,31.75 15.24,27.3 15.88,26.67 15.88,23.5 15.24,22.86 15.24,8.89 13.34,6.99 12.7,6.99 12.7,4.45 J1.12 | v24.13,40.64 24.13,52.07 24.77,52.7 24.77,54.61 25.4,54.61 IC3.7
  Bottom 0.254: v24.13,40.64 17.78,40.64 17.14,40.01 17.14,39.37 16.51,39.37 R1.5

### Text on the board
tPlace: 1541-III V1.1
